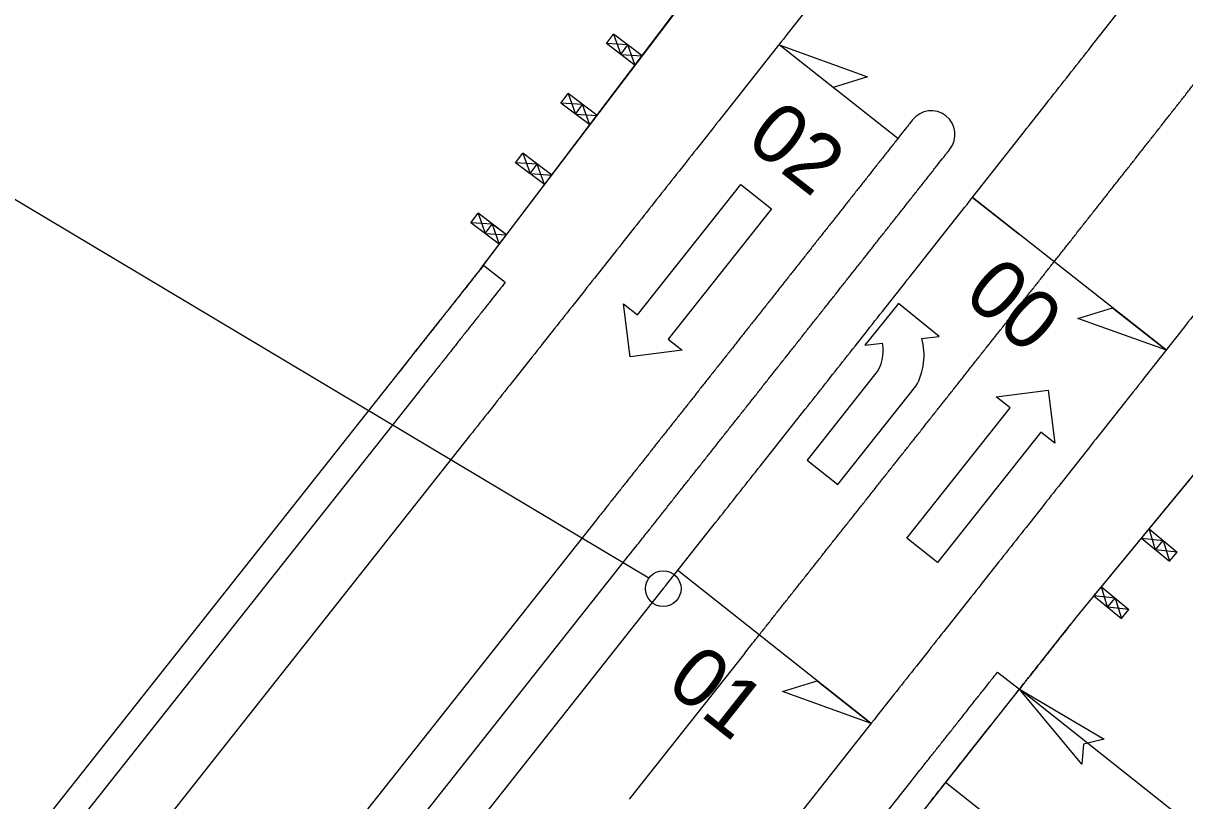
# Model space of a CAD drawing. Extents: x 1778969 to 1790720, y 807089 to 817794.
# Drawn here: x 1782430.2 to 1782528, y 814221.3 to 814286.7 of the extents above; entities that cross this region are included whole.
import ezdxf

# ---------------------------------------------------------------- set-up
doc = ezdxf.new("R2010")
doc.units = 0
for name, color, linetype in [('Prop CMT Guardrail Graphics', 7, 'Continuous'), ('Prop Conc 5in Monolithic Surface Mount Island', 7, 'Continuous'), ('Prop Conc Shoulder Berm Gutter', 7, 'Continuous'), ('Prop Dimension', 7, 'Continuous'), ('Prop EOT', 7, 'Continuous'), ('Prop Guardrail', 7, 'Continuous'), ('Prop Guardrail Anchor Unit CELL', 7, 'Continuous'), ('Prop Horizontal Alignment', 7, 'Continuous'), ('Prop Horizontal Alignment Station Label', 7, 'Continuous'), ('Prop Horizontal Alignment Tick Small', 7, 'Continuous'), ('Prop Lane Arrow CELL', 7, 'Continuous'), ('Prop Lane Lines', 7, 'Continuous'), ('Prop Paved Shoulder', 7, 'Continuous'), ('Prop Superelevation  Arrow CELL', 7, 'Continuous'), ('Prop Superelevation Label', 7, 'Continuous'), ('Prop Terminator CELL', 7, 'Continuous'), ('Scratch_Level_7', 7, 'Continuous')]:
    doc.layers.add(name, color=color, linetype=linetype)

msp = doc.modelspace()

# ---------------------------------------------------------------- linework, layer by layer
at = {"layer": 'Prop CMT Guardrail Graphics'}
for p, q in [((1782468.979, 814266.359), (1782498.95, 814305.949)), ((1782518.73, 814236.557), (1782530.111, 814250.367))]:
    msp.add_line(p, q, dxfattribs=at)
msp.add_open_spline([(1782518.73, 814236.557), (1782518.618, 814236.415), (1782518.505, 814236.273), (1782518.393, 814236.13), (1782517.833, 814235.423), (1782517.273, 814234.716), (1782516.714, 814234.009), (1782516.154, 814233.301), (1782515.595, 814232.594), (1782515.035, 814231.887), (1782514.714, 814231.481), (1782514.393, 814231.076), (1782514.072, 814230.67)], degree=3, dxfattribs=at)
at = {"layer": 'Prop Conc 5in Monolithic Surface Mount Island'}
for p, q in [((1782477.831, 814244.099), (1782441.806, 814198.596)), ((1782477.831, 814244.099), (1782441.806, 814198.596)), ((1782444.942, 814196.113), (1782480.967, 814241.616)), ((1782444.942, 814196.113), (1782480.967, 814241.616))]:
    msp.add_line(p, q, dxfattribs=at)
msp.add_arc((1782506.656, 814277.334), 2, 321.74975, 141.74975, dxfattribs=at)
msp.add_arc((1782506.656, 814277.334), 2, 321.74975, 141.74975, dxfattribs=at)
for points in [[(1782505.085, 814278.572), (1782504.937, 814278.384), (1782504.789, 814278.196), (1782504.641, 814278.008), (1782504.083, 814277.301), (1782503.526, 814276.594), (1782502.968, 814275.887), (1782502.411, 814275.181), (1782501.853, 814274.474), (1782501.295, 814273.767), (1782500.737, 814273.06), (1782500.179, 814272.354), (1782499.622, 814271.647), (1782499.064, 814270.94), (1782498.506, 814270.234), (1782497.947, 814269.527), (1782497.389, 814268.821), (1782496.831, 814268.114), (1782496.273, 814267.408), (1782495.715, 814266.701), (1782495.156, 814265.995), (1782494.598, 814265.288), (1782494.04, 814264.582), (1782493.481, 814263.875), (1782492.923, 814263.169), (1782492.364, 814262.463), (1782491.805, 814261.756), (1782491.247, 814261.05), (1782490.688, 814260.343), (1782490.129, 814259.637), (1782489.571, 814258.931), (1782489.012, 814258.225), (1782488.453, 814257.518), (1782487.894, 814256.812), (1782487.335, 814256.106), (1782486.776, 814255.399), (1782486.218, 814254.693), (1782485.659, 814253.987), (1782485.1, 814253.281), (1782484.541, 814252.574), (1782483.982, 814251.868), (1782483.423, 814251.162), (1782482.863, 814250.455), (1782482.304, 814249.749), (1782481.745, 814249.043), (1782481.186, 814248.337), (1782480.627, 814247.63), (1782480.068, 814246.924), (1782479.509, 814246.218), (1782478.949, 814245.511), (1782478.39, 814244.805), (1782477.831, 814244.099)], [(1782505.085, 814278.572), (1782504.937, 814278.384), (1782504.789, 814278.196), (1782504.641, 814278.008), (1782504.083, 814277.301), (1782503.526, 814276.594), (1782502.968, 814275.887), (1782502.411, 814275.181), (1782501.853, 814274.474), (1782501.295, 814273.767), (1782500.737, 814273.06), (1782500.179, 814272.354), (1782499.622, 814271.647), (1782499.064, 814270.94), (1782498.506, 814270.234), (1782497.947, 814269.527), (1782497.389, 814268.821), (1782496.831, 814268.114), (1782496.273, 814267.408), (1782495.715, 814266.701), (1782495.156, 814265.995), (1782494.598, 814265.288), (1782494.04, 814264.582), (1782493.481, 814263.875), (1782492.923, 814263.169), (1782492.364, 814262.463), (1782491.805, 814261.756), (1782491.247, 814261.05), (1782490.688, 814260.343), (1782490.129, 814259.637), (1782489.571, 814258.931), (1782489.012, 814258.225), (1782488.453, 814257.518), (1782487.894, 814256.812), (1782487.335, 814256.106), (1782486.776, 814255.399), (1782486.218, 814254.693), (1782485.659, 814253.987), (1782485.1, 814253.281), (1782484.541, 814252.574), (1782483.982, 814251.868), (1782483.423, 814251.162), (1782482.863, 814250.455), (1782482.304, 814249.749), (1782481.745, 814249.043), (1782481.186, 814248.337), (1782480.627, 814247.63), (1782480.068, 814246.924), (1782479.509, 814246.218), (1782478.949, 814245.511), (1782478.39, 814244.805), (1782477.831, 814244.099)], [(1782480.967, 814241.616), (1782481.526, 814242.322), (1782482.086, 814243.029), (1782482.645, 814243.735), (1782483.204, 814244.441), (1782483.763, 814245.147), (1782484.322, 814245.854), (1782484.881, 814246.56), (1782485.441, 814247.266), (1782486, 814247.973), (1782486.559, 814248.679), (1782487.118, 814249.385), (1782487.677, 814250.092), (1782488.236, 814250.798), (1782488.795, 814251.504), (1782489.354, 814252.211), (1782489.913, 814252.917), (1782490.472, 814253.624), (1782491.031, 814254.33), (1782491.59, 814255.036), (1782492.149, 814255.743), (1782492.708, 814256.449), (1782493.267, 814257.156), (1782493.825, 814257.862), (1782494.384, 814258.569), (1782494.943, 814259.275), (1782495.502, 814259.982), (1782496.06, 814260.688), (1782496.619, 814261.395), (1782497.177, 814262.101), (1782497.736, 814262.808), (1782498.295, 814263.514), (1782498.853, 814264.221), (1782499.411, 814264.928), (1782499.97, 814265.634), (1782500.528, 814266.341), (1782501.086, 814267.048), (1782501.645, 814267.755), (1782502.203, 814268.461), (1782502.761, 814269.168), (1782503.319, 814269.875), (1782503.877, 814270.582), (1782504.435, 814271.289), (1782504.993, 814271.996), (1782505.551, 814272.703), (1782506.109, 814273.41), (1782506.666, 814274.117), (1782507.224, 814274.824), (1782507.782, 814275.531), (1782507.93, 814275.72), (1782508.078, 814275.908), (1782508.227, 814276.096)], [(1782480.967, 814241.616), (1782481.526, 814242.322), (1782482.086, 814243.029), (1782482.645, 814243.735), (1782483.204, 814244.441), (1782483.763, 814245.147), (1782484.322, 814245.854), (1782484.881, 814246.56), (1782485.441, 814247.266), (1782486, 814247.973), (1782486.559, 814248.679), (1782487.118, 814249.385), (1782487.677, 814250.092), (1782488.236, 814250.798), (1782488.795, 814251.504), (1782489.354, 814252.211), (1782489.913, 814252.917), (1782490.472, 814253.624), (1782491.031, 814254.33), (1782491.59, 814255.036), (1782492.149, 814255.743), (1782492.708, 814256.449), (1782493.267, 814257.156), (1782493.825, 814257.862), (1782494.384, 814258.569), (1782494.943, 814259.275), (1782495.502, 814259.982), (1782496.06, 814260.688), (1782496.619, 814261.395), (1782497.177, 814262.101), (1782497.736, 814262.808), (1782498.295, 814263.514), (1782498.853, 814264.221), (1782499.411, 814264.928), (1782499.97, 814265.634), (1782500.528, 814266.341), (1782501.086, 814267.048), (1782501.645, 814267.755), (1782502.203, 814268.461), (1782502.761, 814269.168), (1782503.319, 814269.875), (1782503.877, 814270.582), (1782504.435, 814271.289), (1782504.993, 814271.996), (1782505.551, 814272.703), (1782506.109, 814273.41), (1782506.666, 814274.117), (1782507.224, 814274.824), (1782507.782, 814275.531), (1782507.93, 814275.72), (1782508.078, 814275.908), (1782508.227, 814276.096)]]:
    msp.add_open_spline(points, degree=3, dxfattribs=at)
at = {"layer": 'Prop Conc Shoulder Berm Gutter'}
for p, q in [((1782468.979, 814266.359), (1782470.814, 814264.907)), ((1782463.392, 814255.53), (1782011.164, 813684.328)), ((1782512.242, 814232.118), (1782514.072, 814230.67)), ((1782322.665, 813992.664), (1782504.815, 814222.736))]:
    msp.add_line(p, q, dxfattribs=at)
for points in [[(1782470.814, 814264.907), (1782470.576, 814264.606), (1782470.338, 814264.305), (1782470.1, 814264.004), (1782469.541, 814263.298), (1782468.982, 814262.592), (1782468.423, 814261.886), (1782467.864, 814261.18), (1782467.305, 814260.474), (1782466.747, 814259.768), (1782466.187, 814259.062), (1782465.628, 814258.355), (1782465.069, 814257.649), (1782464.51, 814256.943), (1782463.951, 814256.237), (1782463.392, 814255.53)], [(1782504.815, 814222.736), (1782505.374, 814223.442), (1782505.933, 814224.148), (1782506.492, 814224.855), (1782507.052, 814225.561), (1782507.611, 814226.268), (1782508.17, 814226.974), (1782508.73, 814227.681), (1782509.289, 814228.388), (1782509.849, 814229.094), (1782510.408, 814229.801), (1782510.968, 814230.508), (1782511.527, 814231.214), (1782511.765, 814231.516), (1782512.004, 814231.817), (1782512.242, 814232.118)], [(1782504.815, 814222.736), (1782505.374, 814223.442), (1782505.933, 814224.148), (1782506.492, 814224.855), (1782507.052, 814225.561), (1782507.611, 814226.268), (1782508.17, 814226.974), (1782508.73, 814227.681), (1782509.289, 814228.388), (1782509.849, 814229.094), (1782510.408, 814229.801), (1782510.968, 814230.508), (1782511.527, 814231.214), (1782511.765, 814231.516), (1782512.004, 814231.817), (1782512.242, 814232.118)]]:
    msp.add_open_spline(points, degree=3, dxfattribs=at)
at = {"layer": 'Prop Dimension'}
for p, q in [((1782553.197, 814199.7), (1782514.072, 814230.67)), ((1782560.391, 814181.239), (1782507.862, 814222.826))]:
    msp.add_line(p, q, dxfattribs=at)
at = {"layer": 'Prop EOT'}
for p, q in [((1782467.835, 814252.013), (1781527.262, 813063.988)), ((1782500.372, 814226.253), (1782270.848, 813936.345))]:
    msp.add_line(p, q, dxfattribs=at)
for points in [[(1782506.028, 814300.39), (1782504.635, 814298.616), (1782502.969, 814296.496), (1782501.303, 814294.377), (1782499.635, 814292.258), (1782497.967, 814290.139), (1782496.298, 814288.021), (1782494.628, 814285.902), (1782492.958, 814283.784), (1782491.287, 814281.666), (1782489.615, 814279.548), (1782487.942, 814277.43), (1782486.269, 814275.312), (1782484.595, 814273.195), (1782482.921, 814271.077), (1782481.246, 814268.959), (1782479.571, 814266.841), (1782477.896, 814264.723), (1782476.22, 814262.605), (1782474.543, 814260.487), (1782472.866, 814258.369), (1782471.189, 814256.251), (1782469.512, 814254.132), (1782467.835, 814252.013)], [(1782543.376, 814280.763), (1782542.289, 814279.376), (1782540.616, 814277.243), (1782538.943, 814275.111), (1782537.27, 814272.979), (1782535.595, 814270.849), (1782533.921, 814268.719), (1782532.245, 814266.59), (1782530.57, 814264.462), (1782528.894, 814262.334), (1782527.217, 814260.208), (1782525.54, 814258.081), (1782523.863, 814255.956), (1782522.186, 814253.831), (1782520.508, 814251.707), (1782518.831, 814249.583), (1782517.153, 814247.46), (1782515.475, 814245.337), (1782513.797, 814243.215), (1782512.118, 814241.094), (1782510.44, 814238.973), (1782508.762, 814236.852), (1782507.084, 814234.731), (1782505.406, 814232.611), (1782503.728, 814230.492), (1782502.05, 814228.372), (1782500.372, 814226.253)]]:
    msp.add_spline(points, degree=3, dxfattribs=at)
at = {"layer": 'Prop Guardrail'}
msp.add_line((1782461.562, 814256.979), (1782009.335, 813685.776), dxfattribs=at)
for points in [[(1782468.766, 814266.078), (1782468.27, 814265.452), (1782466.594, 814263.334), (1782464.917, 814261.216), (1782463.24, 814259.098), (1782461.562, 814256.979)], [(1782506.644, 814221.287), (1782508.322, 814223.406), (1782510, 814225.526), (1782511.678, 814227.646), (1782513.357, 814229.766), (1782515.035, 814231.887), (1782516.714, 814234.009), (1782518.393, 814236.13), (1782518.729, 814236.555)]]:
    msp.add_spline(points, degree=3, dxfattribs=at)
at = {"layer": 'Prop Guardrail Anchor Unit CELL'}
for p, q in [((1782468.766, 814266.078), (1782497.041, 814303.309)), ((1782479.319, 814284.993), (1782479.924, 814285.789)), ((1782482.341, 814283.953), (1782479.924, 814285.789)), ((1782479.924, 814285.789), (1782480.528, 814284.075)), ((1782481.736, 814283.157), (1782479.319, 814284.993)), ((1782481.132, 814284.872), (1782479.319, 814284.993)), ((1782480.528, 814284.075), (1782481.132, 814284.872)), ((1782481.736, 814283.157), (1782481.132, 814284.872)), ((1782480.528, 814284.075), (1782482.341, 814283.953)), ((1782481.736, 814283.157), (1782482.341, 814283.953)), ((1782475.498, 814279.982), (1782476.103, 814280.778)), ((1782478.53, 814278.935), (1782476.103, 814280.778)), ((1782476.103, 814280.778), (1782476.712, 814279.061)), ((1782477.925, 814278.139), (1782475.498, 814279.982)), ((1782477.317, 814279.858), (1782475.498, 814279.982)), ((1782476.712, 814279.061), (1782477.317, 814279.858)), ((1782477.925, 814278.139), (1782477.317, 814279.858)), ((1782476.712, 814279.061), (1782478.53, 814278.935)), ((1782471.683, 814274.967), (1782472.288, 814275.763)), ((1782474.719, 814273.917), (1782472.288, 814275.763)), ((1782472.288, 814275.763), (1782472.899, 814274.044)), ((1782474.114, 814273.121), (1782471.683, 814274.967)), ((1782473.504, 814274.841), (1782471.683, 814274.967)), ((1782472.899, 814274.044), (1782473.504, 814274.841)), ((1782474.114, 814273.121), (1782473.504, 814274.841)), ((1782472.899, 814274.044), (1782474.719, 814273.917)), ((1782518.729, 814236.555), (1782548.461, 814272.634)), ((1782467.914, 814269.917), (1782468.519, 814270.713)), ((1782470.908, 814268.899), (1782468.519, 814270.713)), ((1782468.519, 814270.713), (1782469.108, 814269.01)), ((1782470.303, 814268.103), (1782467.914, 814269.917)), ((1782469.713, 814269.806), (1782467.914, 814269.917)), ((1782469.108, 814269.01), (1782469.713, 814269.806)), ((1782470.908, 814268.899), (1782469.713, 814269.806)), ((1782469.713, 814269.806), (1782470.303, 814268.103)), ((1782469.108, 814269.01), (1782470.908, 814268.899)), ((1782470.303, 814268.103), (1782470.908, 814268.899)), ((1782524.989, 814244.152), (1782527.345, 814242.211)), ((1782525.531, 814242.41), (1782524.989, 814244.152)), ((1782524.353, 814243.38), (1782526.709, 814241.439)), ((1782524.353, 814243.38), (1782526.167, 814243.182)), ((1782525.531, 814242.41), (1782526.167, 814243.182)), ((1782526.167, 814243.182), (1782526.709, 814241.439)), ((1782527.345, 814242.211), (1782525.531, 814242.41)), ((1782526.709, 814241.439), (1782527.345, 814242.211)), ((1782520.346, 814238.517), (1782520.982, 814239.289)), ((1782520.982, 814239.289), (1782523.297, 814237.382)), ((1782520.982, 814239.289), (1782522.139, 814238.335)), ((1782521.503, 814237.563), (1782520.982, 814239.289)), ((1782520.346, 814238.517), (1782522.66, 814236.61)), ((1782522.139, 814238.335), (1782520.346, 814238.517)), ((1782521.503, 814237.563), (1782522.139, 814238.335)), ((1782522.139, 814238.335), (1782522.66, 814236.61)), ((1782523.297, 814237.382), (1782521.503, 814237.563)), ((1782522.66, 814236.61), (1782523.297, 814237.382))]:
    msp.add_line(p, q, dxfattribs=at)
at = {"layer": 'Prop Horizontal Alignment'}
msp.add_line((1782484.103, 814239.133), (1781543.53, 813051.108), dxfattribs=at)
msp.add_arc((1784215.136, 816723.191), 2900, 214.799146, 237.403945, dxfattribs=at)
msp.add_spline([(1782484.103, 814239.133), (1782485.781, 814241.252), (1782487.458, 814243.371), (1782489.136, 814245.49), (1782490.813, 814247.609), (1782492.491, 814249.729), (1782494.168, 814251.848), (1782495.845, 814253.967), (1782497.522, 814256.087), (1782499.198, 814258.207), (1782500.874, 814260.327), (1782502.55, 814262.448), (1782504.225, 814264.569), (1782505.9, 814266.69), (1782507.575, 814268.811), (1782509.249, 814270.933), (1782510.923, 814273.055), (1782512.596, 814275.177), (1782514.268, 814277.3), (1782515.94, 814279.424), (1782517.612, 814281.548), (1782519.282, 814283.672), (1782520.952, 814285.798), (1782522.621, 814287.923), (1782524.29, 814290.049), (1782525.958, 814292.176), (1782527.624, 814294.304), (1782529.29, 814296.432), (1782530.955, 814298.561), (1782532.619, 814300.691), (1782534.283, 814302.821), (1782535.945, 814304.952), (1782537.606, 814307.084), (1782539.266, 814309.217), (1782540.925, 814311.351), (1782542.583, 814313.485), (1782544.239, 814315.621), (1782545.895, 814317.757), (1782547.549, 814319.894), (1782549.202, 814322.033), (1782550.853, 814324.172), (1782552.504, 814326.312), (1782554.152, 814328.454), (1782555.8, 814330.596), (1782557.446, 814332.74), (1782559.09, 814334.885), (1782560.733, 814337.031), (1782562.375, 814339.178), (1782564.015, 814341.326), (1782565.653, 814343.476), (1782567.29, 814345.627), (1782568.925, 814347.779), (1782570.558, 814349.932), (1782572.189, 814352.087), (1782573.819, 814354.243), (1782575.447, 814356.4), (1782577.073, 814358.559), (1782578.697, 814360.72), (1782580.319, 814362.881), (1782581.939, 814365.045), (1782583.558, 814367.209), (1782585.174, 814369.376), (1782586.788, 814371.543), (1782588.4, 814373.713), (1782590.01, 814375.884), (1782591.617, 814378.056), (1782593.223, 814380.23), (1782594.826, 814382.406), (1782596.427, 814384.584), (1782598.025, 814386.763), (1782599.622, 814388.944), (1782601.216, 814391.127), (1782602.807, 814393.311), (1782604.396, 814395.498), (1782605.982, 814397.686)], degree=3, dxfattribs=at)
at = {"layer": 'Prop Horizontal Alignment Station Label'}
msp.add_line((1782482.893, 814240.019), (1782405.187, 814286.383), dxfattribs=at)
msp.add_circle((1782484.103, 814239.133), 1.5, dxfattribs=at)
at = {"layer": 'Prop Horizontal Alignment Tick Small'}
msp.add_line((1782510.13, 814272.049), (1782514.056, 814268.953), dxfattribs=at)
at = {"layer": 'Prop Lane Arrow CELL'}
for p, q in [((1782481.937, 814262.164), (1782490.627, 814273.141)), ((1782490.627, 814273.141), (1782493.215, 814271.092)), ((1782493.215, 814271.092), (1782484.525, 814260.116)), ((1782481.315, 814258.639), (1782480.761, 814263.095)), ((1782480.761, 814263.095), (1782481.937, 814262.164)), ((1782503.904, 814263.119), (1782501.071, 814259.622)), ((1782507.322, 814260.349), (1782503.904, 814263.119)), ((1782484.525, 814260.116), (1782485.701, 814259.185)), ((1782501.071, 814259.622), (1782502.546, 814259.794)), ((1782505.847, 814260.178), (1782507.322, 814260.349)), ((1782485.701, 814259.185), (1782481.315, 814258.639)), ((1782501.896, 814257.12), (1782496.216, 814249.946)), ((1782498.804, 814247.898), (1782505.352, 814256.169)), ((1782512.112, 814255.274), (1782516.497, 814255.819)), ((1782516.497, 814255.819), (1782517.051, 814251.363)), ((1782513.288, 814254.343), (1782512.112, 814255.274)), ((1782504.598, 814243.366), (1782513.288, 814254.343)), ((1782515.875, 814252.294), (1782507.185, 814241.318)), ((1782517.051, 814251.363), (1782515.875, 814252.294)), ((1782496.216, 814249.946), (1782498.804, 814247.898)), ((1782507.185, 814241.318), (1782504.598, 814243.366))]:
    msp.add_line(p, q, dxfattribs=at)
for centre, radius, start, end in [((1782499.348, 814259.15), 3.275, 321.63093, 11.28911), ((1782500.803, 814258.761), 5.253, 330.30701, 15.6187)]:
    msp.add_arc(centre, radius, start, end, dxfattribs=at)
at = {"layer": 'Prop Lane Lines'}
msp.add_line((1782490.964, 814233.702), (1782481.232, 814221.41), dxfattribs=at)
msp.add_open_spline([(1782490.964, 814233.702), (1782491.523, 814234.408), (1782492.082, 814235.114), (1782492.641, 814235.821), (1782493.2, 814236.527), (1782493.76, 814237.234), (1782494.319, 814237.94), (1782494.878, 814238.646), (1782495.437, 814239.353), (1782495.997, 814240.059), (1782496.556, 814240.766), (1782497.115, 814241.472), (1782497.674, 814242.179), (1782498.234, 814242.885), (1782498.793, 814243.592), (1782499.352, 814244.299), (1782499.911, 814245.005), (1782500.471, 814245.712), (1782501.03, 814246.419), (1782501.589, 814247.125), (1782502.148, 814247.832), (1782502.707, 814248.539), (1782503.266, 814249.246), (1782503.825, 814249.952), (1782504.384, 814250.659), (1782504.944, 814251.366), (1782505.503, 814252.073), (1782506.062, 814252.78), (1782506.621, 814253.487), (1782507.18, 814254.194), (1782507.739, 814254.901), (1782508.298, 814255.609), (1782508.856, 814256.316), (1782509.415, 814257.023), (1782509.974, 814257.73), (1782510.533, 814258.438), (1782511.092, 814259.145), (1782511.65, 814259.852), (1782512.209, 814260.56), (1782512.768, 814261.267), (1782513.326, 814261.975), (1782513.885, 814262.683), (1782514.444, 814263.39), (1782515.002, 814264.098), (1782515.561, 814264.806), (1782516.119, 814265.514), (1782516.677, 814266.221), (1782517.236, 814266.929), (1782517.794, 814267.637), (1782518.352, 814268.345), (1782518.91, 814269.053), (1782519.468, 814269.762), (1782520.026, 814270.47), (1782520.584, 814271.178), (1782521.142, 814271.887), (1782521.7, 814272.595), (1782522.258, 814273.303), (1782522.816, 814274.012), (1782523.374, 814274.721), (1782523.931, 814275.429), (1782524.489, 814276.138), (1782525.046, 814276.847), (1782525.604, 814277.556), (1782526.161, 814278.265), (1782526.719, 814278.974), (1782527.276, 814279.683), (1782527.833, 814280.392), (1782528.39, 814281.102), (1782528.947, 814281.811), (1782529.504, 814282.52), (1782530.061, 814283.23), (1782530.618, 814283.939), (1782531.175, 814284.649), (1782531.731, 814285.359), (1782532.288, 814286.069), (1782532.844, 814286.779), (1782533.401, 814287.489), (1782533.957, 814288.199), (1782534.513, 814288.909), (1782535.069, 814289.619), (1782535.626, 814290.329), (1782536.181, 814291.04), (1782536.737, 814291.75), (1782537.293, 814292.461), (1782537.849, 814293.172), (1782538.404, 814293.883), (1782538.96, 814294.593), (1782539.515, 814295.305), (1782539.831, 814295.709), (1782540.147, 814296.113), (1782540.462, 814296.517)], degree=3, dxfattribs=at)
at = {"layer": 'Prop Paved Shoulder'}
for p, q in [((1782468.979, 814266.359), (1782498.95, 814305.949)), ((1782518.73, 814236.557), (1782530.111, 814250.367))]:
    msp.add_line(p, q, dxfattribs=at)
msp.add_open_spline([(1782518.73, 814236.557), (1782518.618, 814236.415), (1782518.505, 814236.273), (1782518.393, 814236.13), (1782517.833, 814235.423), (1782517.273, 814234.716), (1782516.714, 814234.009), (1782516.154, 814233.301), (1782515.595, 814232.594), (1782515.035, 814231.887), (1782514.714, 814231.481), (1782514.393, 814231.076), (1782514.072, 814230.67)], degree=3, dxfattribs=at)
at = {"layer": 'Prop Superelevation  Arrow CELL'}
for p, q in [((1782503.848, 814277.003), (1782493.857, 814284.882)), ((1782526.443, 814259.183), (1782510.13, 814272.049)), ((1782501.59, 814227.792), (1782485.321, 814240.672))]:
    msp.add_line(p, q, dxfattribs=at)
for points in [[(1782493.857, 814284.882), (1782501.295, 814282.201), (1782498.397, 814281.302)], [(1782526.443, 814259.183), (1782519.006, 814261.865), (1782521.904, 814262.763)], [(1782501.59, 814227.792), (1782494.153, 814230.473), (1782497.051, 814231.372)]]:
    msp.add_lwpolyline(points, close=True, dxfattribs=at)
at = {"layer": 'Prop Terminator CELL'}
msp.add_lwpolyline([(1782519.332, 814224.354), (1782514.072, 814230.67), (1782521.205, 814226.483), (1782519.483, 814226.058)], close=True, dxfattribs=at)
at = {"layer": 'Scratch_Level_7'}
for p, q in [((1782461.57, 814256.973), (1782009.342, 813685.77)), ((1782514.064, 814230.676), (1782324.486, 813991.222))]:
    msp.add_line(p, q, dxfattribs=at)
msp.add_open_spline([(1782468.992, 814266.348), (1782468.754, 814266.048), (1782468.516, 814265.747), (1782468.278, 814265.446), (1782467.719, 814264.74), (1782467.161, 814264.034), (1782466.602, 814263.328), (1782466.043, 814262.622), (1782465.484, 814261.916), (1782464.925, 814261.21), (1782464.366, 814260.504), (1782463.807, 814259.798), (1782463.248, 814259.091), (1782462.689, 814258.385), (1782462.129, 814257.679), (1782461.57, 814256.973)], degree=3, dxfattribs=at)

# ---------------------------------------------------------------- texts
at = {"layer": 'Prop Superelevation Label'}
for s, rotation, p in [('02', 322.03519, (1782490.884, 814276.562)), ('00', 318.9698, (1782509.215, 814263.588)), ('01', 321.7104, (1782484.171, 814230.82))]:
    msp.add_text(s, height=5, rotation=rotation, dxfattribs=at).set_placement(p)

doc.saveas('drawing.dxf')
